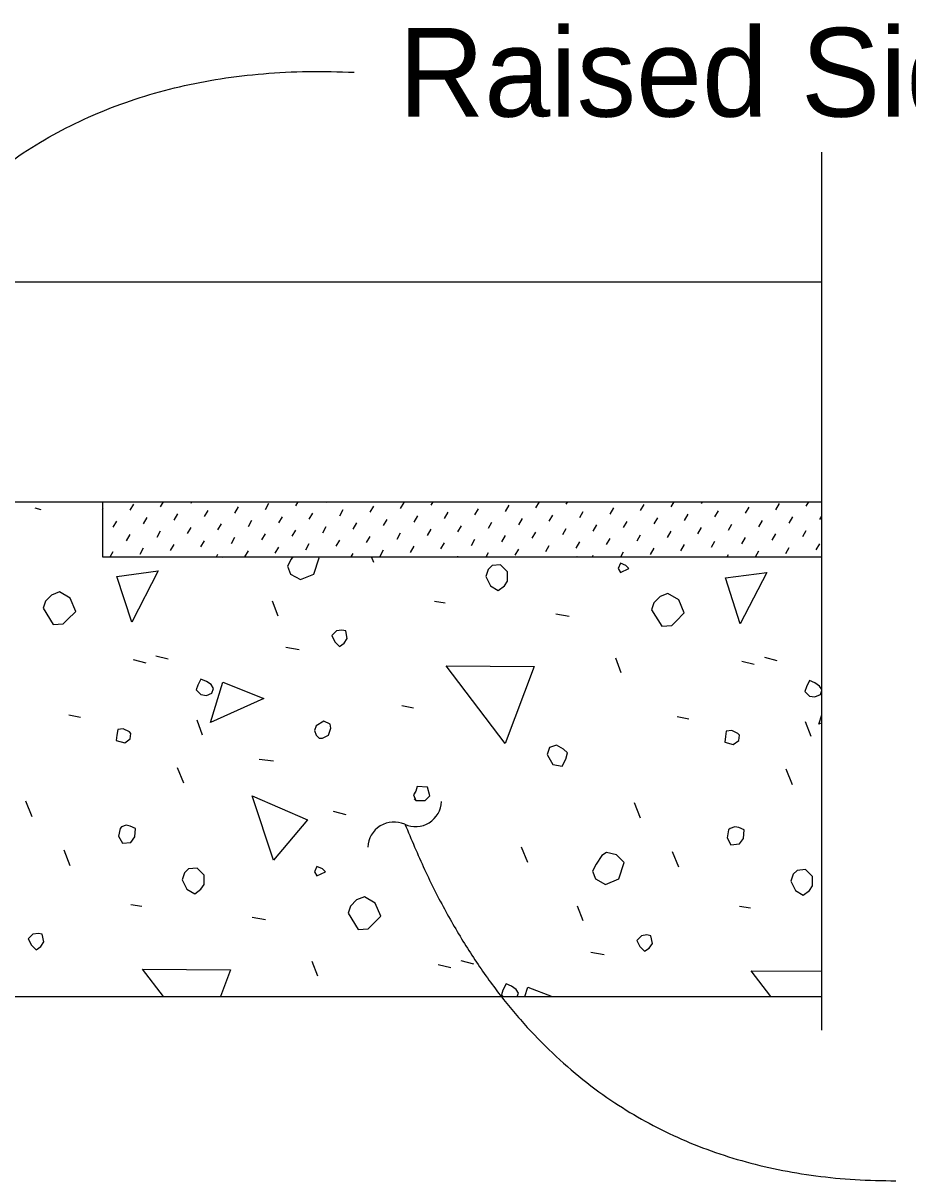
# Model space of a CAD drawing. Extents: x 0 to 40.8, y 1 to 28.
# Drawn here: x 21.611 to 23.621, y 9.611 to 12.242 of the extents above; entities that cross this region are included whole.
import ezdxf

# ---------------------------------------------------------------- set-up
doc = ezdxf.new("R2010")
doc.units = 0
for name, color, linetype in [('Dimension', 7, 'Continuous'), ('Miscellaneous', 7, 'Continuous'), ('TextStructures', 7, 'Continuous'), ('TrafBarrierConc', 7, 'Continuous')]:
    doc.layers.add(name, color=color, linetype=linetype)

msp = doc.modelspace()

# ---------------------------------------------------------------- linework, layer by layer
at = {"layer": 'Dimension'}
msp.add_lwpolyline([(23.4254, 9.9535), (23.4254, 11.9492)], dxfattribs=at)
for centre, start, end in [((22.5023, 10.4756), 245.9128, 357.64), ((22.4537, 10.3668), 65.9128, 177.64)]:
    msp.add_arc(centre, 0.0596, start, end, dxfattribs=at)
for points in [[(21.1298, 11.3348), (21.4903, 12.1705), (22.3635, 12.1307)], [(22.4787, 10.4216), (22.8019, 9.6109), (23.5941, 9.6109)]]:
    msp.add_open_spline(points, degree=2, dxfattribs=at)
at = {"layer": 'Miscellaneous'}
for p, q in [((21.6376, 11.1402), (21.6511, 11.1368)), ((21.7913, 11.1372), (21.7934, 11.1409)), ((21.8545, 11.1351), (21.8626, 11.1491)), ((21.9236, 11.1432), (21.9302, 11.1545)), ((21.9928, 11.1513), (21.9947, 11.1545)), ((22.0233, 11.1207), (22.0314, 11.1347)), ((22.0925, 11.1288), (22.1006, 11.1428)), ((22.1616, 11.1369), (22.1697, 11.1509)), ((22.2308, 11.145), (22.2363, 11.1545)), ((22.3, 11.1531), (22.3008, 11.1545)), ((22.3305, 11.1226), (22.3386, 11.1366)), ((22.3997, 11.1307), (22.4078, 11.1447)), ((22.4688, 11.1388), (22.4769, 11.1528)), ((22.538, 11.1469), (22.5424, 11.1545)), ((22.6377, 11.1245), (22.6458, 11.1385)), ((22.7069, 11.1326), (22.715, 11.1466)), ((22.776, 11.1407), (22.784, 11.1545)), ((22.8452, 11.1488), (22.8485, 11.1545)), ((22.8757, 11.1183), (22.8838, 11.1323)), ((22.9449, 11.1264), (22.953, 11.1404)), ((23.014, 11.1345), (23.0221, 11.1485)), ((23.0832, 11.1426), (23.0901, 11.1545)), ((23.1524, 11.1507), (23.1546, 11.1545)), ((23.1829, 11.1201), (23.191, 11.1341)), ((23.2521, 11.1282), (23.2602, 11.1422)), ((23.3212, 11.1363), (23.3293, 11.1503)), ((23.3904, 11.1444), (23.3962, 11.1545)), ((21.8158, 11.0964), (21.8239, 11.1104)), ((21.885, 11.1045), (21.8931, 11.1185)), ((21.9542, 11.1126), (21.9623, 11.1266)), ((22.0538, 11.0902), (22.062, 11.1042)), ((22.123, 11.0983), (22.1311, 11.1123)), ((22.1922, 11.1064), (22.2003, 11.1204)), ((22.2613, 11.1145), (22.2694, 11.1285)), ((22.361, 11.0921), (22.3691, 11.1061)), ((22.4302, 11.1002), (22.4383, 11.1142)), ((22.4994, 11.1083), (22.5075, 11.1223)), ((22.5685, 11.1164), (22.5766, 11.1304)), ((22.6682, 11.094), (22.6763, 11.1079)), ((22.7374, 11.1021), (22.7455, 11.1161)), ((22.8065, 11.1102), (22.8147, 11.1242)), ((22.9754, 11.0958), (22.9835, 11.1098)), ((23.0446, 11.1039), (23.0527, 11.1179)), ((23.1137, 11.112), (23.1218, 11.126)), ((23.2826, 11.0977), (23.2907, 11.1117)), ((23.3518, 11.1058), (23.3599, 11.1198)), ((23.4209, 11.1139), (23.4254, 11.1217)), ((21.8464, 11.0659), (21.8545, 11.0799)), ((21.9155, 11.074), (21.9236, 11.088)), ((21.9847, 11.0821), (21.9928, 11.0961)), ((22.1535, 11.0678), (22.1616, 11.0818)), ((22.2227, 11.0759), (22.2308, 11.0899)), ((22.2919, 11.084), (22.3, 11.098)), ((22.4607, 11.0696), (22.4688, 11.0836)), ((22.5299, 11.0778), (22.538, 11.0917)), ((22.5991, 11.0859), (22.6072, 11.0998)), ((22.7679, 11.0715), (22.776, 11.0855)), ((22.8371, 11.0796), (22.8452, 11.0936)), ((22.9062, 11.0877), (22.9143, 11.1017)), ((23.0059, 11.0653), (23.014, 11.0793)), ((23.0751, 11.0734), (23.0832, 11.0874)), ((23.1443, 11.0815), (23.1524, 11.0955)), ((23.2134, 11.0896), (23.2215, 11.1036)), ((23.3131, 11.0672), (23.3212, 11.0812)), ((23.3823, 11.0753), (23.3904, 11.0893)), ((21.9461, 11.0435), (21.9542, 11.0575)), ((22.0152, 11.0516), (22.0233, 11.0656)), ((22.0844, 11.0597), (22.0925, 11.0737)), ((22.2532, 11.0453), (22.2613, 11.0593)), ((22.3224, 11.0534), (22.3305, 11.0674)), ((22.3916, 11.0615), (22.3997, 11.0755)), ((22.4913, 11.0391), (22.4994, 11.0531)), ((22.5604, 11.0472), (22.5685, 11.0612)), ((22.6296, 11.0553), (22.6377, 11.0693)), ((22.6988, 11.0634), (22.7069, 11.0774)), ((22.7984, 11.041), (22.8065, 11.055)), ((22.8676, 11.0491), (22.8757, 11.0631)), ((22.9368, 11.0572), (22.9449, 11.0712)), ((23.1056, 11.0429), (23.1137, 11.0569)), ((23.1748, 11.051), (23.1829, 11.065)), ((23.244, 11.0591), (23.2521, 11.0731)), ((23.4128, 11.0448), (23.4209, 11.0587)), ((21.809, 11.0295), (21.8158, 11.0413)), ((21.8769, 11.0354), (21.885, 11.0494)), ((22.0507, 11.0295), (22.0538, 11.035)), ((22.0647, 11.0272), (22.0638, 11.0295)), ((22.1151, 11.0295), (22.123, 11.0431)), ((22.1841, 11.0372), (22.1922, 11.0512)), ((22.3568, 11.0295), (22.361, 11.0369)), ((22.4077, 11.0166), (22.4025, 11.0295)), ((22.4221, 11.031), (22.4302, 11.045)), ((22.5984, 11.0295), (22.5991, 11.0307)), ((22.6629, 11.0295), (22.6682, 11.0388)), ((22.7293, 11.0329), (22.7374, 11.0469)), ((22.9045, 11.0295), (22.9062, 11.0326)), ((22.969, 11.0295), (22.9754, 11.0407)), ((23.0365, 11.0348), (23.0446, 11.0488)), ((23.2106, 11.0295), (23.2134, 11.0344)), ((23.2751, 11.0295), (23.2826, 11.0425)), ((23.3437, 11.0366), (23.3518, 11.0506)), ((22.1903, 10.8946), (22.1779, 10.9282)), ((22.5456, 10.9282), (22.5703, 10.9247)), ((22.8214, 10.8999), (22.8514, 10.8946)), ((22.2079, 10.8239), (22.238, 10.8186)), ((21.8615, 10.7956), (21.8897, 10.7886)), ((21.9127, 10.8045), (21.941, 10.7974)), ((22.9698, 10.7656), (22.9575, 10.7992)), ((23.2438, 10.7921), (23.2721, 10.785)), ((23.2951, 10.801), (23.3234, 10.7939)), ((22.4713, 10.6913), (22.4978, 10.686)), ((21.7147, 10.6701), (21.7412, 10.6648)), ((22.0188, 10.6242), (22.0064, 10.6578)), ((23.0971, 10.6666), (23.1236, 10.6613)), ((23.4012, 10.6206), (23.3888, 10.6542)), ((22.1478, 10.5694), (22.1797, 10.5658)), ((21.9764, 10.5146), (21.9622, 10.5499)), ((23.3588, 10.511), (23.3446, 10.5464)), ((21.6316, 10.4386), (21.6175, 10.4739)), ((22.3158, 10.4509), (22.3441, 10.4439)), ((23.014, 10.435), (22.9999, 10.4704)), ((22.7577, 10.3343), (22.7436, 10.3696)), ((21.7183, 10.3272), (21.7041, 10.3625)), ((23.1007, 10.3237), (23.0865, 10.359)), ((21.8561, 10.2388), (21.8809, 10.2353)), ((22.1319, 10.2105), (22.162, 10.2052)), ((22.8832, 10.2017), (22.8708, 10.2353)), ((23.2385, 10.2353), (23.2633, 10.2317)), ((22.9009, 10.131), (22.931, 10.1257)), ((22.2804, 10.0762), (22.268, 10.1098)), ((22.6057, 10.1115), (22.634, 10.1044)), ((22.5544, 10.1027), (22.5827, 10.0956))]:
    msp.add_line(p, q, dxfattribs=at)
for points in [[(22.224, 11.0295), (22.2203, 11.0237), (22.2115, 11.0078), (22.2185, 10.9901)], [(22.2185, 10.9901), (22.2415, 10.9777), (22.2716, 10.9901), (22.2839, 11.0272), (22.2817, 11.0295)], [(22.8691, 11.029), (22.8689, 11.0295)], [(22.8695, 11.0295), (22.8691, 11.029)], [(22.6623, 10.9848), (22.6729, 10.9636), (22.6905, 10.953), (22.7047, 10.9636), (22.7117, 10.9742), (22.7117, 10.9954), (22.6958, 11.0113), (22.6764, 11.0095), (22.6676, 11.0007), (22.6623, 10.9848)], [(22.9681, 10.9936), (22.9875, 11.0025), (22.9804, 11.0095), (22.9681, 11.0148), (22.9628, 11.0025), (22.9681, 10.9936)], [(21.8579, 10.8805), (21.8243, 10.9848), (21.918, 10.9972), (21.8579, 10.8805)], [(23.2403, 10.877), (23.2067, 10.9813), (23.3004, 10.9936), (23.2403, 10.877)], [(21.6564, 10.9123), (21.6794, 10.8752), (21.7024, 10.877), (21.7112, 10.8858), (21.7306, 10.9052), (21.7183, 10.9353), (21.6935, 10.9494), (21.6758, 10.9424), (21.6617, 10.9282), (21.6564, 10.9123)], [(23.0388, 10.9088), (23.0618, 10.8717), (23.0847, 10.8734), (23.0936, 10.8823), (23.113, 10.9017), (23.1007, 10.9318), (23.0759, 10.9459), (23.0582, 10.9388), (23.0441, 10.9247), (23.0388, 10.9088)], [(22.3193, 10.8363), (22.3299, 10.8257), (22.3405, 10.8328), (22.3476, 10.8434), (22.3441, 10.8611), (22.3352, 10.8628), (22.3228, 10.8611), (22.3122, 10.8504), (22.3193, 10.8363)], [(22.7064, 10.6047), (22.5721, 10.7815), (22.7719, 10.7797), (22.7064, 10.6047)], [(22.0152, 10.7161), (22.0276, 10.7143), (22.04, 10.7196), (22.0435, 10.7302), (22.0382, 10.7391), (22.0276, 10.7461), (22.0152, 10.7515), (22.0082, 10.7373), (22.0046, 10.7267), (22.0152, 10.7161)], [(22.0365, 10.6525), (22.0647, 10.7444), (22.1584, 10.7073), (22.0365, 10.6525)], [(23.4254, 10.7275), (23.4206, 10.7355), (23.41, 10.7426), (23.3976, 10.7479), (23.3906, 10.7338), (23.387, 10.7232), (23.3976, 10.7126)], [(23.3976, 10.7126), (23.41, 10.7108), (23.4224, 10.7161), (23.4254, 10.7252)], [(23.4189, 10.6489), (23.4254, 10.6703)], [(21.8226, 10.6118), (21.842, 10.6065), (21.8544, 10.6153), (21.8561, 10.6277), (21.8526, 10.6312), (21.8385, 10.6383), (21.8261, 10.6365), (21.8243, 10.6242), (21.8226, 10.6118)], [(22.2839, 10.6171), (22.291, 10.6171), (22.3052, 10.6242), (22.3105, 10.6401), (22.3087, 10.6489), (22.2946, 10.656), (22.2769, 10.6454), (22.2733, 10.6348), (22.2769, 10.6242), (22.2839, 10.6171)], [(23.205, 10.6083), (23.2244, 10.603), (23.2368, 10.6118), (23.2385, 10.6242), (23.235, 10.6277), (23.2209, 10.6348), (23.2085, 10.633), (23.2067, 10.6206), (23.205, 10.6083)], [(23.4254, 10.6519), (23.4189, 10.6489)], [(22.8054, 10.5729), (22.8143, 10.557), (22.8355, 10.5535), (22.8443, 10.5694), (22.8479, 10.5835), (22.839, 10.5924), (22.8231, 10.6012), (22.8072, 10.5959), (22.8019, 10.58), (22.8054, 10.5729)], [(22.5032, 10.4757), (22.5244, 10.4757), (22.535, 10.4863), (22.5297, 10.5057), (22.5067, 10.5075), (22.5032, 10.4969), (22.4978, 10.4881), (22.5032, 10.4757), (22.4996, 10.4792)], [(22.1797, 10.3396), (22.1319, 10.4863), (22.2574, 10.4315), (22.1797, 10.3396)], [(21.8279, 10.3944), (21.8367, 10.3785), (21.8561, 10.3802), (21.865, 10.3926), (21.8668, 10.412), (21.8544, 10.4173), (21.8455, 10.4191), (21.8349, 10.4156), (21.8314, 10.412), (21.8279, 10.3944)], [(23.2103, 10.3908), (23.2191, 10.3749), (23.2385, 10.3767), (23.2474, 10.3891), (23.2492, 10.4085), (23.2368, 10.4138), (23.2279, 10.4156), (23.2173, 10.412), (23.2138, 10.4085), (23.2103, 10.3908)], [(22.9115, 10.2971), (22.9345, 10.2848), (22.9645, 10.2971), (22.9769, 10.3343), (22.9592, 10.3519), (22.9363, 10.3572), (22.9256, 10.3502), (22.9133, 10.3307), (22.9044, 10.3148), (22.9115, 10.2971)], [(21.9728, 10.2954), (21.9834, 10.2742), (22.0011, 10.2635), (22.0152, 10.2742), (22.0223, 10.2848), (22.0223, 10.306), (22.0064, 10.3219), (21.987, 10.3201), (21.9781, 10.3113), (21.9728, 10.2954)], [(22.2786, 10.3042), (22.2981, 10.313), (22.291, 10.3201), (22.2786, 10.3254), (22.2733, 10.313), (22.2786, 10.3042)], [(23.3552, 10.2918), (23.3658, 10.2706), (23.3835, 10.26), (23.3976, 10.2706), (23.4047, 10.2812), (23.4047, 10.3024), (23.3888, 10.3183), (23.3694, 10.3166), (23.3605, 10.3077), (23.3552, 10.2918)], [(22.3494, 10.2194), (22.3723, 10.1822), (22.3953, 10.184), (22.4042, 10.1928), (22.4236, 10.2123), (22.4112, 10.2423), (22.3865, 10.2565), (22.3688, 10.2494), (22.3547, 10.2353), (22.3494, 10.2194)], [(21.6299, 10.1469), (21.6405, 10.1363), (21.6511, 10.1433), (21.6582, 10.1539), (21.6546, 10.1716), (21.6458, 10.1734), (21.6334, 10.1716), (21.6228, 10.161), (21.6299, 10.1469)], [(23.0123, 10.1433), (23.0229, 10.1327), (23.0335, 10.1398), (23.0406, 10.1504), (23.037, 10.1681), (23.0282, 10.1699), (23.0158, 10.1681), (23.0052, 10.1575), (23.0123, 10.1433)], [(21.9302, 10.0295), (21.8827, 10.0921), (22.0824, 10.0903), (22.0597, 10.0295)], [(23.3099, 10.0295), (23.2651, 10.0885), (23.4254, 10.0871)], [(22.7339, 10.0295), (22.7365, 10.0373), (22.7312, 10.0461), (22.7206, 10.0532), (22.7082, 10.0585), (22.7011, 10.0443), (22.6976, 10.0337), (22.7018, 10.0295)], [(22.751, 10.0295), (22.7577, 10.0514), (22.813, 10.0295)]]:
    msp.add_lwpolyline(points, dxfattribs=at)
at = {"layer": 'TrafBarrierConc'}
for p, q in [((19.7913, 11.6545), (23.4254, 11.6545)), ((19.7913, 11.1545), (23.4254, 11.1545)), ((21.7913, 11.1545), (21.7913, 11.0295)), ((21.7913, 11.0295), (23.4254, 11.0295)), ((21.4086, 10.0295), (23.4254, 10.0295))]:
    msp.add_line(p, q, dxfattribs=at)

# ---------------------------------------------------------------- texts
at = {"layer": 'TextStructures'}
msp.add_text('Raised Sidewalk', height=0.2016, dxfattribs=at).set_placement((22.4642, 12.0298))

doc.saveas('drawing.dxf')
